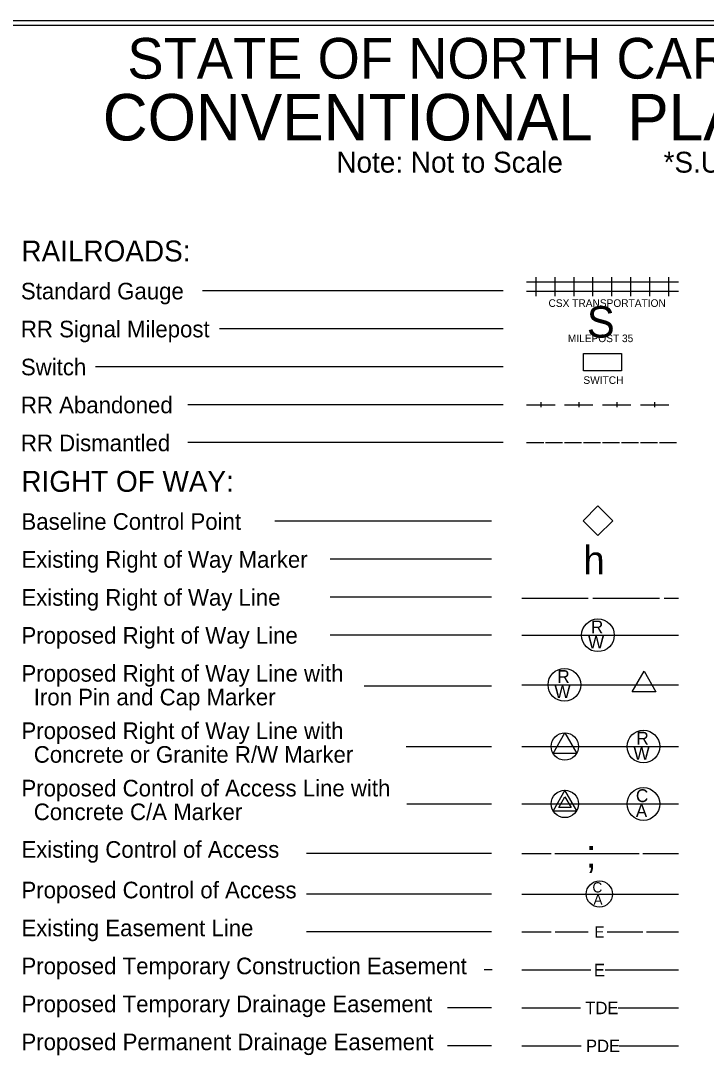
# Model space of a CAD drawing. Extents: x 2241278 to 2254132, y 649924 to 670434.
# Drawn here: x 2247365 to 2249172, y 658059 to 660787 of the extents above; entities that cross this region are included whole.
import ezdxf

# ---------------------------------------------------------------- set-up
doc = ezdxf.new("R2010")
doc.units = 0
for name, color, linetype in [('Sheet Data Text CELL', 7, 'Continuous'), ('Sheet Plot Border Inside CELL', 7, 'Continuous'), ('Sheet Symbology CELL', 7, 'Continuous')]:
    doc.layers.add(name, color=color, linetype=linetype)

msp = doc.modelspace()

# ---------------------------------------------------------------- linework, layer by layer
at = {"layer": 'Sheet Data Text CELL'}
msp.add_lwpolyline([(2248847.9, 659469.7), (2248887, 659508.8), (2248926.1, 659469.7), (2248887, 659430.6)], close=True, dxfattribs=at)
at = {"layer": 'Sheet Plot Border Inside CELL'}
msp.add_lwpolyline([(2244623.8, 655511.4), (2252956.3, 655511.4), (2252956.3, 660786.9), (2244623.8, 660786.9)], close=True, dxfattribs=at)
at = {"layer": 'Sheet Symbology CELL'}
for p, q in [((2248723.8, 660061.8), (2248723.8, 660111.8)), ((2248773.8, 660061.8), (2248773.8, 660111.8)), ((2248823.8, 660061.8), (2248823.8, 660111.8)), ((2248873.8, 660061.8), (2248873.8, 660111.8)), ((2248923.8, 660061.8), (2248923.8, 660111.8)), ((2248973.8, 660061.8), (2248973.8, 660111.8)), ((2249023.8, 660061.8), (2249023.8, 660111.8)), ((2249073.8, 660061.8), (2249073.8, 660111.8)), ((2248698.8, 660099.3), (2248748.8, 660099.3)), ((2248748.8, 660099.3), (2248798.8, 660099.3)), ((2248798.8, 660099.3), (2248848.8, 660099.3)), ((2248848.8, 660099.3), (2248898.8, 660099.3)), ((2248898.8, 660099.3), (2248948.8, 660099.3)), ((2248948.8, 660099.3), (2248998.8, 660099.3)), ((2248998.8, 660099.3), (2249048.8, 660099.3)), ((2249048.8, 660099.3), (2249098.8, 660099.3)), ((2248636.8, 660075.5), (2247844.7, 660075.5)), ((2248698.8, 660074.3), (2248748.8, 660074.3)), ((2248748.8, 660074.3), (2248798.8, 660074.3)), ((2248798.8, 660074.3), (2248848.8, 660074.3)), ((2248848.8, 660074.3), (2248898.8, 660074.3)), ((2248898.8, 660074.3), (2248948.8, 660074.3)), ((2248948.8, 660074.3), (2248998.8, 660074.3)), ((2248998.8, 660074.3), (2249048.8, 660074.3)), ((2249048.8, 660074.3), (2249098.8, 660074.3)), ((2248636.8, 659975.5), (2247889.1, 659975.5)), ((2248636.8, 659875.5), (2247562.2, 659875.5)), ((2248636.8, 659775.5), (2247806, 659775.5)), ((2248698.8, 659775.5), (2248773.8, 659775.5)), ((2248736.3, 659781.8), (2248736.3, 659769.3)), ((2248798.8, 659775.5), (2248873.8, 659775.5)), ((2248836.3, 659781.8), (2248836.3, 659769.3)), ((2248898.8, 659775.5), (2248973.8, 659775.5)), ((2248936.3, 659781.8), (2248936.3, 659769.3)), ((2248998.8, 659775.5), (2249073.8, 659775.5)), ((2249036.3, 659781.8), (2249036.3, 659769.3)), ((2248636.8, 659675.5), (2247806, 659675.5)), ((2248636.8, 659675.5), (2247806, 659675.5)), ((2248698.8, 659675.5), (2248743.8, 659675.5)), ((2248748.8, 659675.5), (2248793.8, 659675.5)), ((2248798.8, 659675.5), (2248843.8, 659675.5)), ((2248848.8, 659675.5), (2248893.8, 659675.5)), ((2248898.8, 659675.5), (2248943.8, 659675.5)), ((2248948.8, 659675.5), (2248993.8, 659675.5)), ((2248998.8, 659675.5), (2249043.8, 659675.5)), ((2249048.8, 659675.5), (2249093.8, 659675.5)), ((2248606.1, 659468.8), (2248035.1, 659468.8)), ((2248606.1, 659368.8), (2248181.4, 659368.8)), ((2248606.1, 659268.8), (2248181.4, 659268.8)), ((2248686.3, 659265.9), (2248861.3, 659265.9)), ((2248873.8, 659265.9), (2249048.8, 659265.9)), ((2249061.3, 659265.9), (2249098.8, 659265.9)), ((2248606.1, 659168.8), (2248181.4, 659168.8)), ((2248686.3, 659168.1), (2249098.8, 659168.1)), ((2248606.1, 659034.5), (2248270.6, 659034.5)), ((2248686.3, 659037.5), (2249098.8, 659037.5)), ((2249008.5, 659037.5), (2249008.5, 659037.5)), ((2248606.1, 658874.3), (2248381.2, 658874.3)), ((2248686.3, 658875), (2249098.8, 658875)), ((2248799.8, 658875), (2248799.8, 658875)), ((2248606.1, 658723.1), (2248383, 658723.1)), ((2248686.3, 658723.8), (2249098.8, 658723.8)), ((2248799.8, 658723.8), (2248799.8, 658723.8)), ((2248606.1, 658593.4), (2248118.4, 658593.4)), ((2248686.3, 658593.4), (2248763.6, 658593.4)), ((2248773.6, 658593.4), (2248995.6, 658593.4)), ((2249005.6, 658593.4), (2249098.8, 658593.4)), ((2248606.1, 658486.6), (2248118.4, 658486.6)), ((2248686.3, 658486.6), (2249098.8, 658486.6)), ((2248606.1, 658386.6), (2248118.4, 658386.6)), ((2248686.3, 658386.6), (2248763.8, 658386.6)), ((2248773.8, 658386.6), (2248861.3, 658386.6)), ((2248911.3, 658386.6), (2249005.1, 658386.6)), ((2249015.1, 658386.6), (2249098.8, 658386.6)), ((2248608, 658286.6), (2248587.2, 658286.6)), ((2248686.3, 658286.6), (2248699.3, 658286.6)), ((2248699.3, 658286.6), (2248868.1, 658286.6)), ((2248905.6, 658286.6), (2249074.3, 658286.6)), ((2249074.3, 658286.6), (2249098.8, 658286.6)), ((2248606.1, 658186.6), (2248490.4, 658186.6)), ((2248686.3, 658186.6), (2248703, 658186.6)), ((2248703, 658186.6), (2248840.5, 658186.6)), ((2248940.5, 658186.6), (2249078, 658186.6)), ((2249078, 658186.6), (2249098.8, 658186.6)), ((2248606.1, 658086.6), (2248490.4, 658086.6)), ((2248686.3, 658086.6), (2248705.3, 658086.6)), ((2248705.3, 658086.6), (2248842.8, 658086.6)), ((2248942.8, 658086.6), (2249080.3, 658086.6)), ((2249080.3, 658086.6), (2249098.8, 658086.6))]:
    msp.add_line(p, q, dxfattribs=at)
for points in [[(2252893.8, 660774.2), (2245393.8, 660774.2), (2245393.8, 655529.3), (2252893.8, 655529.3)], [(2248848.8, 659910.3), (2248948.8, 659910.3), (2248948.8, 659864.8), (2248848.8, 659864.8)], [(2248977.3, 659019.5), (2249008.5, 659073.5), (2249039.8, 659019.5)], [(2248768.5, 658857), (2248799.8, 658911), (2248831, 658857)], [(2248768.5, 658705.8), (2248831, 658705.8), (2248799.8, 658759.8)], [(2248783.4, 658714.4), (2248799.8, 658742.6), (2248816.1, 658714.4)]]:
    msp.add_lwpolyline(points, close=True, dxfattribs=at)
for centre, radius in [((2248886.9, 659168.1), 43.1), ((2248798.4, 659037.5), 43.1), ((2249006.7, 658875), 43.1), ((2248799.7, 658875), 36), ((2248799.7, 658723.8), 36), ((2249006.7, 658723.8), 43.1), ((2248890.6, 658486.6), 34.5)]:
    msp.add_circle(centre, radius, dxfattribs=at)

# ---------------------------------------------------------------- texts
for s, height, p in [('STATE OF NORTH CAROLINA, DIVISION OF HIGHWAYS', 107.095, (2247646.6, 660634.4)), ('CONVENTIONAL  PLAN SHEET SYMBOLS', 122.402, (2247581.8, 660471.5)), ('RAILROADS:', 55, (2247367.4, 660152.8)), ('Standard Gauge', 43.75, (2247366, 660052.9)), ('S', 82.5, (2248857.6, 659952.4)), ('RR Signal Milepost', 43.75, (2247366, 659952.9)), ('Switch', 43.75, (2247366, 659852.9)), ('RR Abandoned', 43.75, (2247366, 659752.9)), ('RR Dismantled', 43.75, (2247366, 659652.9)), ('RIGHT OF WAY:', 55, (2247367.4, 659546)), ('Baseline Control Point', 43.75, (2247367.4, 659446)), ('h', 75, (2248848.8, 659328.4)), ('Existing Right of Way Marker', 43.75, (2247367.4, 659346)), ('Existing Right of Way Line', 43.75, (2247367.4, 659246)), ('Proposed Right of Way Line', 43.75, (2247367.4, 659146)), ('R', 33.8, (2248868.3, 659173.2)), ('W', 33.8, (2248860.6, 659133.4)), ('Proposed Right of Way Line with', 43.75, (2247367.4, 659046)), ('R', 33.8, (2248779.8, 659042.6)), ('  Iron Pin and Cap Marker', 43.75, (2247367.4, 658983.5)), ('W', 33.8, (2248772.1, 659002.8)), ('Proposed Right of Way Line with', 43.75, (2247367.4, 658894.9)), ('R', 33.8, (2248988.2, 658880.1)), ('  Concrete or Granite R/W Marker', 43.75, (2247367.4, 658832.4)), ('W', 33.8, (2248980.5, 658840.3)), ('Proposed Control of Access Line with', 43.75, (2247367.4, 658743.7)), ('C', 33.8, (2248986.9, 658728.8)), ('  Concrete C/A Marker', 43.75, (2247367.4, 658681.2)), ('A', 33.8, (2248986.6, 658689.1)), ('Existing Control of Access', 43.75, (2247367.4, 658582.1)), (';', 75, (2248855, 658555.9)), ('Proposed Control of Access', 43.75, (2247367.4, 658475.3)), ('C', 27, (2248872.3, 658490.7)), ('A', 27, (2248875, 658458.2)), ('Existing Easement Line', 43.75, (2247367.4, 658375.3)), ('E', 30, (2248877.3, 658371.6)), ('Proposed Temporary Construction Easement', 43.75, (2247367.4, 658275.3)), ('E', 32.7, (2248876.1, 658270.1)), ('Proposed Temporary Drainage Easement', 43.75, (2247367.4, 658175.3)), ('TDE', 32.75, (2248853.5, 658170.1)), ('Proposed Permanent Drainage Easement', 43.75, (2247367.4, 658075.3)), ('PDE', 32.75, (2248855.3, 658070.1))]:
    msp.add_text(s, height=height, dxfattribs=at).set_placement(p)
for s, height, p in [('Note: Not to Scale', 55, (2248197.5, 660386.7)), ('*S.U.E. = Subsurface Utility Engineering', 55, (2249059.9, 660386.7)), ('CSX TRANSPORTATION', 20, (2248756.6, 660033.1)), ('MILEPOST 35', 20, (2248807.5, 659940.3)), ('SWITCH', 20, (2248848.5, 659830.3))]:
    msp.add_text(s, height=height, rotation=360, dxfattribs=at).set_placement(p)

doc.saveas('drawing.dxf')
